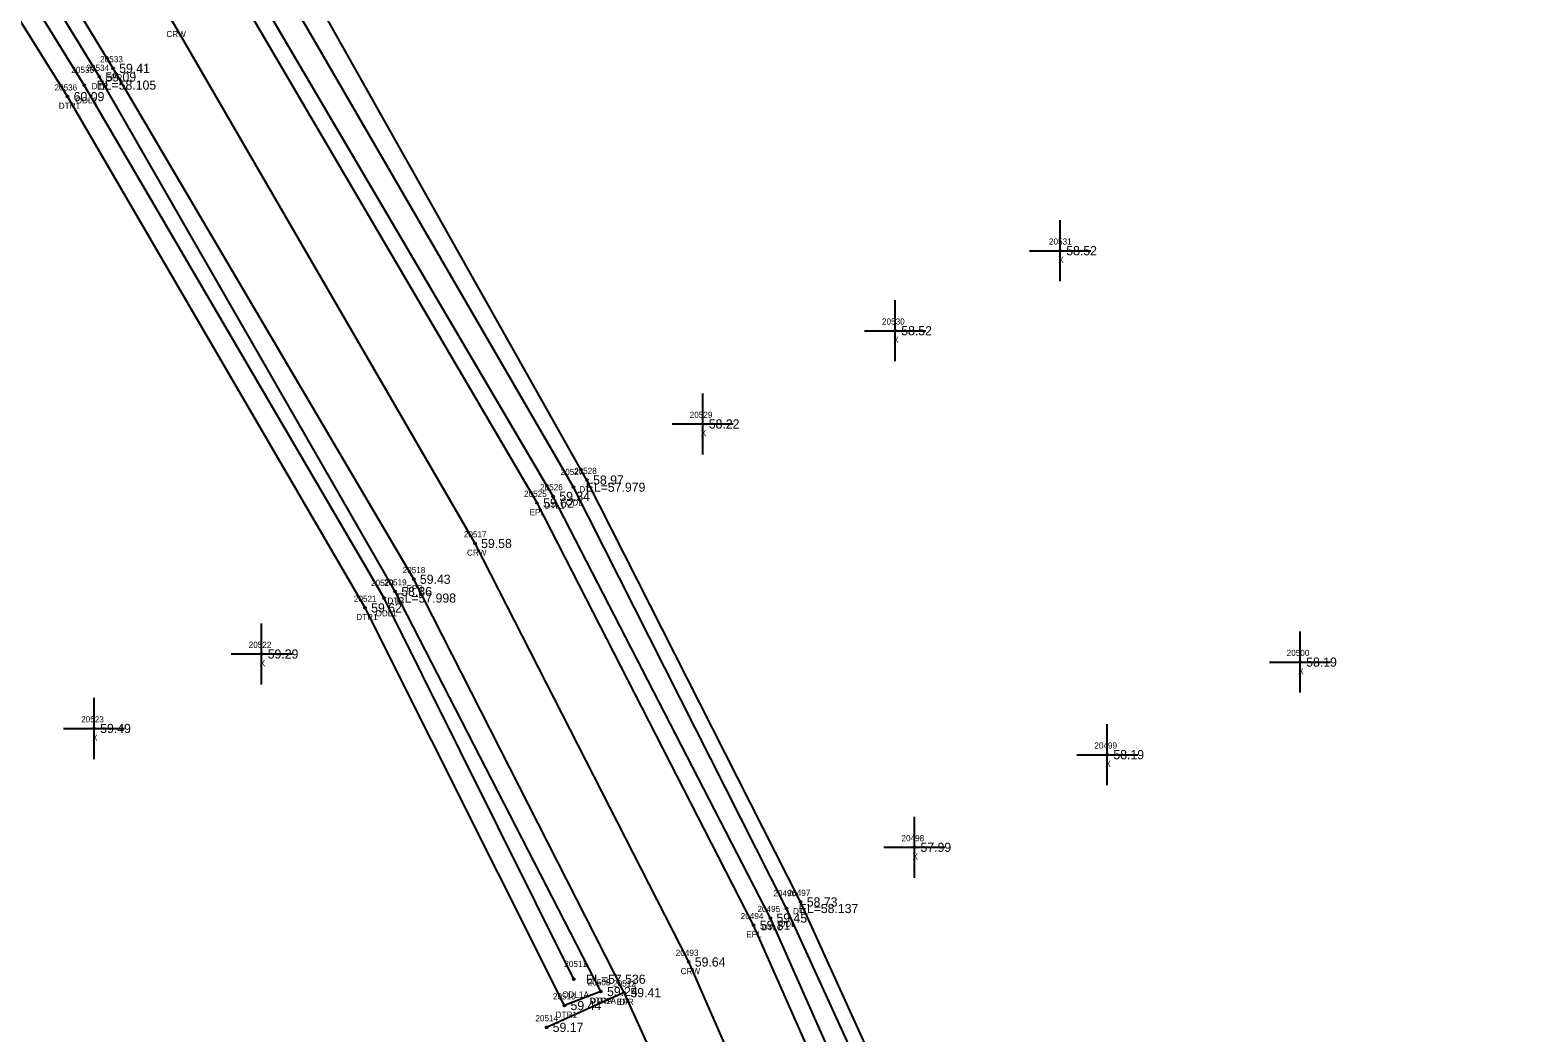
# Model space of a CAD drawing. Extents: x 2396547 to 2397655, y 770185 to 772649.
# Drawn here: x 2397339.4 to 2397586.1, y 770555.1 to 770719.1 of the extents above; entities that cross this region are included whole.
import ezdxf

# ---------------------------------------------------------------- set-up
doc = ezdxf.new("R2010")
doc.units = 0
for name, color, linetype in [('RD_DTM_BkLn1', 7, 'Continuous'), ('RD_EX_Driveway', 7, 'Continuous'), ('RD_EX_Driveway_txCode', 7, 'Continuous'), ('RD_EX_H2O', 7, 'Continuous'), ('RD_EX_H2O_txCode', 7, 'Continuous'), ('RD_EX_Misc', 7, 'Continuous'), ('RD_EX_Misc_txCode', 7, 'Continuous'), ('RD_EX_Road', 7, 'Continuous'), ('RD_EX_Road_txCode', 7, 'Continuous'), ('RD_EX_TX_Driveway_ELEV', 7, 'Continuous'), ('RD_EX_TX_H2O_ELEV', 7, 'Continuous'), ('RD_EX_TX_Misc_ELEV', 7, 'Continuous'), ('RD_EX_TX_Road_ELEV', 7, 'Continuous'), ('RD_HC_Survey_ELEV', 7, 'Continuous'), ('RD_HC_Survey_txCode', 7, 'Continuous'), ('RD_SMD_Locator', 7, 'Continuous')]:
    doc.layers.add(name, color=color, linetype=linetype)

msp = doc.modelspace()

# ---------------------------------------------------------------- linework, layer by layer
at = {"layer": 'RD_DTM_BkLn1'}
msp.add_lwpolyline([(2397565.46, 770206.19), (2397547.69, 770280.33), (2397528.11, 770352.94), (2397504.84, 770424.66), (2397476.69, 770499.34), (2397447.19, 770566.69), (2397412.23, 770635.13), (2397363.03, 770719.95), (2397270.14, 770871.5)], dxfattribs=at)
at = {"layer": 'RD_EX_Driveway'}
msp.add_line((2397436.66, 770561.67), (2397423.94, 770555.99), dxfattribs=at)
at = {"layer": 'RD_EX_H2O'}
for points in [[(2397586.15, 770211.51), (2397567.31, 770287.61), (2397548.79, 770357.79), (2397525.19, 770434.22), (2397495.53, 770510.39), (2397465.51, 770576.5), (2397430.55, 770645.5), (2397380.29, 770734.7), (2397327.01, 770824.44), (2397291.42, 770882.36)], [(2397579.43, 770209.93), (2397561.1, 770285.3), (2397543.19, 770356.19), (2397518.98, 770431.67), (2397489.88, 770507.8), (2397460.56, 770573.86), (2397425.02, 770642.83), (2397373.6, 770730.3), (2397319.08, 770819.92), (2397284.14, 770878.8)], [(2397583.73, 770210.91), (2397565.2, 770287.05), (2397546.34, 770357.13), (2397522.25, 770433.23), (2397493.26, 770509.76), (2397463.19, 770575.43), (2397428.34, 770644.33), (2397377.24, 770732.42), (2397321.77, 770821.7), (2397287.01, 770879.96)], [(2397428.38, 770563.87), (2397397.36, 770626.2), (2397348.29, 770710.09), (2397290.43, 770803.51), (2397255.11, 770861.71)], [(2397432.83, 770561.85), (2397399.16, 770627.27), (2397350.75, 770711.42), (2397293.36, 770805.09), (2397257.48, 770863.23)], [(2397432.83, 770561.85), (2397426.86, 770559.56), (2397394.23, 770624.59), (2397345.55, 770708.21), (2397287.31, 770801.51), (2397251.15, 770859.33)]]:
    msp.add_lwpolyline(points, dxfattribs=at)
at = {"layer": 'RD_EX_Misc'}
for p, q in [((2397507.98, 770678.01), (2397507.98, 770688.01)), ((2397502.98, 770683.01), (2397512.98, 770683.01)), ((2397480.98, 770664.93), (2397480.98, 770674.93)), ((2397475.98, 770669.93), (2397485.98, 770669.93)), ((2397449.48, 770649.67), (2397449.48, 770659.67)), ((2397444.48, 770654.67), (2397454.48, 770654.67)), ((2397377.3, 770612.06), (2397377.3, 770622.06)), ((2397547.24, 770610.73), (2397547.24, 770620.73)), ((2397372.3, 770617.06), (2397382.3, 770617.06)), ((2397542.24, 770615.73), (2397552.24, 770615.73)), ((2397349.89, 770599.88), (2397349.89, 770609.88)), ((2397344.89, 770604.88), (2397354.89, 770604.88)), ((2397515.69, 770595.59), (2397515.69, 770605.59)), ((2397510.69, 770600.59), (2397520.69, 770600.59)), ((2397484.13, 770580.44), (2397484.13, 770590.44)), ((2397479.13, 770585.44), (2397489.13, 770585.44))]:
    msp.add_line(p, q, dxfattribs=at)
at = {"layer": 'RD_EX_Road'}
for points in [[(2397576.88, 770209.21), (2397558.85, 770284.47), (2397539.93, 770354.87), (2397515.81, 770430.13), (2397486.97, 770506.75), (2397457.82, 770572.7), (2397422.37, 770641.75), (2397371.16, 770729.12), (2397316.57, 770818.52), (2397280.76, 770876.73)], [(2397553.19, 770205.48), (2397535.12, 770280.96), (2397517, 770349.24), (2397493.4, 770422.78), (2397467.13, 770492.9), (2397441.16, 770551.74), (2397436.66, 770561.67), (2397402.21, 770629.28), (2397353, 770712.83), (2397296, 770806.32), (2397260.16, 770864.73)]]:
    msp.add_lwpolyline(points, dxfattribs=at)
at = {"layer": 'RD_SMD_Locator'}
for centre in [(2397353, 770712.83), (2397350.75, 770711.42), (2397345.55, 770708.21), (2397348.29, 770710.09), (2397507.98, 770683.01), (2397480.98, 770669.93), (2397449.48, 770654.67), (2397428.34, 770644.33), (2397430.55, 770645.5), (2397422.37, 770641.75), (2397425.02, 770642.83), (2397412.23, 770635.13), (2397402.21, 770629.28), (2397399.16, 770627.27), (2397394.23, 770624.59), (2397397.36, 770626.2), (2397377.3, 770617.06), (2397547.24, 770615.73), (2397349.89, 770604.88), (2397515.69, 770600.59), (2397484.13, 770585.44), (2397463.19, 770575.43), (2397465.51, 770576.5), (2397457.82, 770572.7), (2397460.56, 770573.86), (2397447.19, 770566.69), (2397428.38, 770563.87), (2397432.83, 770561.85), (2397432.83, 770561.85), (2397436.66, 770561.67), (2397436.66, 770561.67), (2397426.86, 770559.56), (2397423.94, 770555.99)]:
    msp.add_circle(centre, 0.15, dxfattribs=at)

# ---------------------------------------------------------------- texts
at = {"layer": 'RD_EX_Driveway_txCode'}
for s, p in [('20513', (2397434.82, 770562.67)), ('DA', (2397435.86, 770559.67)), ('20514', (2397422.11, 770556.99))]:
    msp.add_text(s, height=1, dxfattribs=at).set_placement(p)
at = {"layer": 'RD_EX_H2O_txCode'}
for s, p in [('20535', (2397346.17, 770712.09)), ('20534', (2397348.63, 770712.42)), ('DTR', (2397349.48, 770709.42)), ('20536', (2397343.41, 770709.21)), ('ODL1', (2397346.88, 770707.09)), ('DTR1', (2397344.11, 770706.21)), ('20527', (2397426.23, 770646.33)), ('20528', (2397428.43, 770646.5)), ('20526', (2397422.87, 770643.83)), ('DTL', (2397429.3, 770643.5)), ('DTL1', (2397423.61, 770640.83)), ('ODL', (2397427.1, 770641.33)), ('20520', (2397395.21, 770628.2)), ('20519', (2397397.32, 770628.27)), ('20521', (2397392.4, 770625.59)), ('ODL1', (2397395.95, 770623.2)), ('DTR', (2397397.89, 770625.27)), ('DTR1', (2397392.8, 770622.59)), ('20496', (2397461.05, 770577.43)), ('20497', (2397463.39, 770577.5)), ('20495', (2397458.44, 770574.86)), ('DTL', (2397464.27, 770574.5)), ('DTL1', (2397459.15, 770571.86)), ('ODL', (2397461.95, 770572.43)), ('20511', (2397426.83, 770565.87)), ('20508', (2397430.67, 770562.85)), ('20509', (2397430.67, 770562.85)), ('20510', (2397424.98, 770560.56)), ('ODL1A', (2397426.48, 770560.87)), ('DTR1A', (2397430.91, 770559.85)), ('DTRA', (2397431.07, 770559.85)), ('DTR1', (2397425.42, 770557.56))]:
    msp.add_text(s, height=1, dxfattribs=at).set_placement(p)
at = {"layer": 'RD_EX_Misc_txCode'}
for s, p in [('20531', (2397506.14, 770684.01)), ('X', (2397507.66, 770681.01)), ('20530', (2397478.82, 770670.93)), ('X', (2397480.66, 770667.93)), ('20529', (2397447.36, 770655.67)), ('X', (2397449.16, 770652.67)), ('20522', (2397375.19, 770618.06)), ('20500', (2397545.04, 770616.73)), ('X', (2397376.99, 770615.06)), ('X', (2397546.93, 770613.73)), ('20523', (2397347.77, 770605.88)), ('X', (2397349.57, 770602.88)), ('20499', (2397513.57, 770601.59)), ('X', (2397515.37, 770598.59)), ('20498', (2397482.01, 770586.44)), ('X', (2397483.82, 770583.44))]:
    msp.add_text(s, height=1, dxfattribs=at).set_placement(p)
at = {"layer": 'RD_EX_Road_txCode'}
for s, p in [('20533', (2397350.88, 770713.83)), ('EPR', (2397351.77, 770710.83)), ('20525', (2397420.25, 770642.75)), ('EPL', (2397421.16, 770639.75)), ('20518', (2397400.38, 770630.28)), ('EPR', (2397400.98, 770627.28)), ('20494', (2397455.7, 770573.7)), ('EPL', (2397456.61, 770570.7)), ('20512', (2397434.82, 770562.67)), ('EPR', (2397435.43, 770559.67))]:
    msp.add_text(s, height=1, dxfattribs=at).set_placement(p)
at = {"layer": 'RD_EX_TX_Driveway_ELEV'}
for s, p in [('59.41', (2397437.66, 770560.92)), ('59.17', (2397424.94, 770555.24))]:
    msp.add_text(s, height=1.5, dxfattribs=at).set_placement(p)
at = {"layer": 'RD_EX_TX_H2O_ELEV'}
for s, p in [('EL=58.105', (2397350.29, 770709.34)), ('59.09', (2397351.75, 770710.67)), ('60.09', (2397346.55, 770707.46)), ('58.97', (2397431.55, 770644.75)), ('EL=57.979', (2397430.34, 770643.58)), ('59.34', (2397426.02, 770642.08)), ('EL=57.998', (2397399.36, 770625.45)), ('58.86', (2397400.16, 770626.52)), ('59.62', (2397395.23, 770623.84)), ('58.73', (2397466.51, 770575.75)), ('EL=58.137', (2397465.19, 770574.68)), ('59.45', (2397461.56, 770573.11)), ('EL=57.536', (2397430.38, 770563.12)), ('59.24', (2397433.83, 770561.1)), ('59.24', (2397433.83, 770561.1)), ('59.44', (2397427.86, 770558.81))]:
    msp.add_text(s, height=1.5, dxfattribs=at).set_placement(p)
at = {"layer": 'RD_EX_TX_Misc_ELEV'}
for s, p in [('58.52', (2397508.98, 770682.26)), ('58.52', (2397481.98, 770669.18)), ('58.22', (2397450.48, 770653.92)), ('59.29', (2397378.3, 770616.31)), ('58.19', (2397548.24, 770614.98)), ('59.49', (2397350.89, 770604.13)), ('58.19', (2397516.69, 770599.84)), ('57.99', (2397485.13, 770584.69))]:
    msp.add_text(s, height=1.5, dxfattribs=at).set_placement(p)
at = {"layer": 'RD_EX_TX_Road_ELEV'}
for s, p in [('59.41', (2397354, 770712.08)), ('59.62', (2397423.37, 770641)), ('59.43', (2397403.21, 770628.53)), ('59.81', (2397458.82, 770571.95)), ('59.41', (2397437.66, 770560.92))]:
    msp.add_text(s, height=1.5, dxfattribs=at).set_placement(p)
at = {"layer": 'RD_HC_Survey_ELEV'}
for s, p in [('59.58', (2397413.23, 770634.38)), ('59.64', (2397448.19, 770565.94))]:
    msp.add_text(s, height=1.5, dxfattribs=at).set_placement(p)
at = {"layer": 'RD_HC_Survey_txCode'}
for s, p in [('CRW', (2397361.72, 770717.95)), ('20517', (2397410.4, 770636.13)), ('CRW', (2397410.91, 770633.13)), ('20493', (2397445.07, 770567.69)), ('CRW', (2397445.87, 770564.69))]:
    msp.add_text(s, height=1, dxfattribs=at).set_placement(p)

doc.saveas('drawing.dxf')
